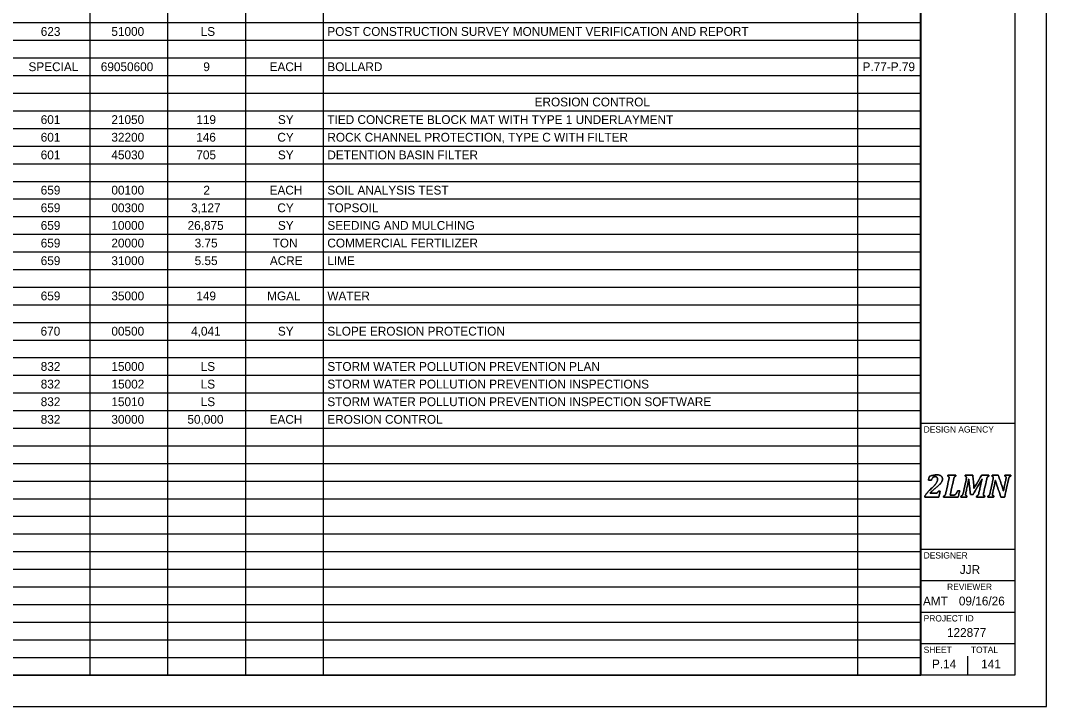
# Model space of a CAD drawing. Extents: x 0 to 34, y 0 to 22.
# Drawn here: x 17.71 to 34, y 0 to 10.89 of the extents above; entities that cross this region are included whole.
import ezdxf

# ---------------------------------------------------------------- set-up
doc = ezdxf.new("R2010")
doc.units = 0
for name, color, linetype in [('SH_Border', 7, 'Continuous'), ('SH_Cut_Line', 7, 'Continuous'), ('SH_Data', 7, 'Continuous'), ('SH_Text', 7, 'Continuous')]:
    doc.layers.add(name, color=color, linetype=linetype)

msp = doc.modelspace()

# ---------------------------------------------------------------- linework, layer by layer
at = {"layer": 'SH_Border'}
for p, q in [((32, 0.5), (32, 21.5)), ((32, 4.5), (33.5, 4.5)), ((32, 2.5), (33.5, 2.5)), ((32, 2), (33.5, 2)), ((32, 1.5), (33.5, 1.5)), ((32, 1), (33.5, 1))]:
    msp.add_line(p, q, dxfattribs=at)
msp.add_lwpolyline([(1.5, 21.5), (33.5, 21.5), (33.5, 0.5), (1.5, 0.5)], close=True, dxfattribs=at)
at = {"layer": 'SH_Cut_Line'}
msp.add_lwpolyline([(0, 0), (34, 0), (34, 22), (0, 22)], close=True, dxfattribs=at)
at = {"layer": 'SH_Data'}
for p, q in [((32.75, 3.5), (32.75, 3.5)), ((32.375, 0.675), (32.375, 0.675)), ((32.75, 0.5), (32.75, 0.8))]:
    msp.add_line(p, q, dxfattribs=at)
for points in [[(32.237, 3.388), (32.246, 3.388), (32.253, 3.389), (32.258, 3.39), (32.263, 3.392), (32.267, 3.394), (32.27, 3.397), (32.273, 3.401), (32.277, 3.408), (32.281, 3.417), (32.281, 3.417), (32.312, 3.417), (32.312, 3.417), (32.312, 3.417), (32.29, 3.326), (32.29, 3.326), (32.29, 3.326), (32.066, 3.326), (32.066, 3.326), (32.066, 3.326), (32.069, 3.343), (32.069, 3.343), (32.078, 3.358), (32.091, 3.375), (32.106, 3.394), (32.122, 3.412), (32.144, 3.435), (32.172, 3.462), (32.197, 3.486), (32.217, 3.506), (32.23, 3.521), (32.243, 3.537), (32.253, 3.551), (32.259, 3.566), (32.266, 3.58), (32.269, 3.595), (32.269, 3.61), (32.269, 3.622), (32.266, 3.632), (32.26, 3.64), (32.253, 3.647), (32.245, 3.65), (32.234, 3.65), (32.22, 3.65), (32.208, 3.646), (32.198, 3.636), (32.188, 3.627), (32.18, 3.613), (32.172, 3.593), (32.172, 3.593), (32.126, 3.593), (32.126, 3.593), (32.126, 3.593), (32.14, 3.654), (32.14, 3.654), (32.166, 3.663), (32.188, 3.669), (32.205, 3.673), (32.223, 3.676), (32.24, 3.678), (32.258, 3.678), (32.278, 3.678), (32.295, 3.675), (32.309, 3.669), (32.322, 3.664), (32.332, 3.656), (32.339, 3.646), (32.345, 3.637), (32.348, 3.626), (32.348, 3.613), (32.348, 3.602), (32.346, 3.591), (32.342, 3.581), (32.339, 3.571), (32.333, 3.56), (32.324, 3.549), (32.315, 3.539), (32.304, 3.526), (32.289, 3.513), (32.275, 3.499), (32.254, 3.482), (32.228, 3.46), (32.216, 3.45), (32.202, 3.438), (32.188, 3.425), (32.174, 3.412), (32.162, 3.4), (32.154, 3.391), (32.154, 3.391), (32.153, 3.388), (32.153, 3.388), (32.153, 3.388), (32.237, 3.388), (32.237, 3.388)], [(32.237, 3.388), (32.237, 3.388), (32.153, 3.388), (32.153, 3.388), (32.153, 3.388), (32.154, 3.391), (32.154, 3.391), (32.162, 3.4), (32.174, 3.412), (32.188, 3.425), (32.202, 3.438), (32.216, 3.45), (32.228, 3.46), (32.254, 3.482), (32.275, 3.499), (32.289, 3.513), (32.304, 3.526), (32.315, 3.539), (32.324, 3.549), (32.333, 3.56), (32.339, 3.571), (32.342, 3.581), (32.346, 3.591), (32.348, 3.602), (32.348, 3.613), (32.348, 3.626), (32.345, 3.637), (32.339, 3.646), (32.332, 3.656), (32.322, 3.664), (32.309, 3.669), (32.295, 3.675), (32.278, 3.678), (32.258, 3.678), (32.24, 3.678), (32.223, 3.676), (32.205, 3.673), (32.188, 3.669), (32.166, 3.663), (32.14, 3.654), (32.14, 3.654), (32.126, 3.593), (32.126, 3.593), (32.126, 3.593), (32.172, 3.593), (32.172, 3.593), (32.18, 3.613), (32.188, 3.627), (32.198, 3.636), (32.208, 3.646), (32.22, 3.65), (32.234, 3.65), (32.245, 3.65), (32.253, 3.647), (32.26, 3.64), (32.266, 3.632), (32.269, 3.622), (32.269, 3.61), (32.269, 3.595), (32.266, 3.58), (32.259, 3.566), (32.253, 3.551), (32.243, 3.537), (32.23, 3.521), (32.217, 3.506), (32.197, 3.486), (32.172, 3.462), (32.144, 3.435), (32.122, 3.412), (32.106, 3.394), (32.091, 3.375), (32.078, 3.358), (32.069, 3.343), (32.069, 3.343), (32.066, 3.326), (32.066, 3.326), (32.066, 3.326), (32.29, 3.326), (32.29, 3.326), (32.29, 3.326), (32.312, 3.417), (32.312, 3.417), (32.312, 3.417), (32.281, 3.417), (32.281, 3.417), (32.277, 3.408), (32.273, 3.401), (32.27, 3.397), (32.267, 3.394), (32.263, 3.392), (32.258, 3.39), (32.253, 3.389), (32.246, 3.388), (32.237, 3.388)], [(32.518, 3.356), (32.527, 3.356), (32.533, 3.357), (32.538, 3.358), (32.542, 3.36), (32.546, 3.362), (32.55, 3.365), (32.554, 3.368), (32.558, 3.372), (32.562, 3.377), (32.567, 3.382), (32.571, 3.388), (32.576, 3.397), (32.58, 3.405), (32.585, 3.415), (32.589, 3.427), (32.589, 3.427), (32.624, 3.427), (32.624, 3.427), (32.624, 3.427), (32.598, 3.326), (32.598, 3.326), (32.598, 3.326), (32.365, 3.326), (32.365, 3.326), (32.365, 3.326), (32.369, 3.343), (32.369, 3.343), (32.376, 3.345), (32.381, 3.348), (32.385, 3.351), (32.389, 3.355), (32.392, 3.36), (32.395, 3.366), (32.398, 3.373), (32.4, 3.382), (32.403, 3.395), (32.403, 3.395), (32.449, 3.605), (32.449, 3.605), (32.452, 3.615), (32.453, 3.625), (32.453, 3.635), (32.453, 3.642), (32.451, 3.647), (32.448, 3.651), (32.444, 3.654), (32.439, 3.656), (32.432, 3.657), (32.432, 3.657), (32.435, 3.674), (32.435, 3.674), (32.435, 3.674), (32.563, 3.674), (32.563, 3.674), (32.563, 3.674), (32.559, 3.657), (32.559, 3.657), (32.552, 3.655), (32.547, 3.652), (32.543, 3.649), (32.539, 3.645), (32.536, 3.64), (32.533, 3.634), (32.531, 3.627), (32.528, 3.618), (32.525, 3.605), (32.525, 3.605), (32.47, 3.356), (32.47, 3.356), (32.47, 3.356), (32.518, 3.356), (32.518, 3.356)], [(32.518, 3.356), (32.518, 3.356), (32.47, 3.356), (32.47, 3.356), (32.47, 3.356), (32.525, 3.605), (32.525, 3.605), (32.528, 3.618), (32.531, 3.627), (32.533, 3.634), (32.536, 3.64), (32.539, 3.645), (32.543, 3.649), (32.547, 3.652), (32.552, 3.655), (32.559, 3.657), (32.559, 3.657), (32.563, 3.674), (32.563, 3.674), (32.563, 3.674), (32.435, 3.674), (32.435, 3.674), (32.435, 3.674), (32.432, 3.657), (32.432, 3.657), (32.439, 3.656), (32.444, 3.654), (32.448, 3.651), (32.451, 3.647), (32.453, 3.642), (32.453, 3.635), (32.453, 3.625), (32.452, 3.615), (32.449, 3.605), (32.449, 3.605), (32.403, 3.395), (32.403, 3.395), (32.4, 3.382), (32.398, 3.373), (32.395, 3.366), (32.392, 3.36), (32.389, 3.355), (32.385, 3.351), (32.381, 3.348), (32.376, 3.345), (32.369, 3.343), (32.369, 3.343), (32.365, 3.326), (32.365, 3.326), (32.365, 3.326), (32.598, 3.326), (32.598, 3.326), (32.598, 3.326), (32.624, 3.427), (32.624, 3.427), (32.624, 3.427), (32.589, 3.427), (32.589, 3.427), (32.585, 3.415), (32.58, 3.405), (32.576, 3.397), (32.571, 3.388), (32.567, 3.382), (32.562, 3.377), (32.558, 3.372), (32.554, 3.368), (32.55, 3.365), (32.546, 3.362), (32.542, 3.36), (32.538, 3.358), (32.533, 3.357), (32.527, 3.356), (32.518, 3.356)], [(32.829, 3.674), (32.829, 3.674), (32.849, 3.461), (32.849, 3.461), (32.849, 3.461), (32.969, 3.674), (32.969, 3.674), (32.969, 3.674), (33.087, 3.674), (33.087, 3.674), (33.087, 3.674), (33.084, 3.657), (33.084, 3.657), (33.077, 3.655), (33.071, 3.652), (33.067, 3.649), (33.064, 3.645), (33.06, 3.64), (33.058, 3.634), (33.055, 3.627), (33.052, 3.618), (33.05, 3.605), (33.05, 3.605), (33.003, 3.395), (33.003, 3.395), (33.002, 3.39), (33.002, 3.387), (33.001, 3.384), (33.001, 3.382), (33.001, 3.379), (33, 3.376), (33, 3.373), (33, 3.369), (33, 3.365), (33, 3.358), (33.002, 3.353), (33.005, 3.349), (33.008, 3.346), (33.014, 3.344), (33.021, 3.343), (33.021, 3.343), (33.018, 3.326), (33.018, 3.326), (33.018, 3.326), (32.89, 3.326), (32.89, 3.326), (32.89, 3.326), (32.893, 3.343), (32.893, 3.343), (32.9, 3.345), (32.906, 3.348), (32.91, 3.351), (32.914, 3.355), (32.917, 3.36), (32.919, 3.366), (32.922, 3.373), (32.925, 3.382), (32.928, 3.395), (32.928, 3.395), (32.951, 3.502), (32.951, 3.502), (32.954, 3.513), (32.957, 3.529), (32.962, 3.548), (32.967, 3.568), (32.972, 3.588), (32.978, 3.609), (32.978, 3.609), (32.973, 3.609), (32.973, 3.609), (32.965, 3.594), (32.957, 3.579), (32.948, 3.563), (32.948, 3.563), (32.833, 3.364), (32.833, 3.364), (32.833, 3.364), (32.792, 3.364), (32.792, 3.364), (32.792, 3.364), (32.775, 3.518), (32.775, 3.518), (32.773, 3.537), (32.772, 3.554), (32.77, 3.569), (32.769, 3.583), (32.768, 3.597), (32.768, 3.611), (32.768, 3.611), (32.764, 3.611), (32.764, 3.611), (32.761, 3.596), (32.758, 3.578), (32.755, 3.558), (32.751, 3.538), (32.747, 3.521), (32.744, 3.507), (32.744, 3.507), (32.72, 3.395), (32.72, 3.395), (32.719, 3.39), (32.718, 3.387), (32.718, 3.384), (32.717, 3.382), (32.717, 3.379), (32.717, 3.376), (32.717, 3.373), (32.716, 3.369), (32.716, 3.365), (32.716, 3.358), (32.718, 3.353), (32.721, 3.349), (32.725, 3.346), (32.73, 3.344), (32.738, 3.343), (32.738, 3.343), (32.734, 3.326), (32.734, 3.326), (32.734, 3.326), (32.641, 3.326), (32.641, 3.326), (32.641, 3.326), (32.644, 3.343), (32.644, 3.343), (32.651, 3.345), (32.657, 3.348), (32.661, 3.351), (32.665, 3.355), (32.668, 3.36), (32.67, 3.366), (32.673, 3.373), (32.676, 3.382), (32.679, 3.395), (32.679, 3.395), (32.725, 3.605), (32.725, 3.605), (32.727, 3.615), (32.728, 3.625), (32.728, 3.635), (32.728, 3.642), (32.727, 3.647), (32.723, 3.651), (32.72, 3.654), (32.715, 3.656), (32.707, 3.657), (32.707, 3.657), (32.711, 3.674), (32.711, 3.674), (32.711, 3.674), (32.829, 3.674), (32.829, 3.674)], [(32.829, 3.674), (32.829, 3.674), (32.711, 3.674), (32.711, 3.674), (32.711, 3.674), (32.707, 3.657), (32.707, 3.657), (32.715, 3.656), (32.72, 3.654), (32.723, 3.651), (32.727, 3.647), (32.728, 3.642), (32.728, 3.635), (32.728, 3.625), (32.727, 3.615), (32.725, 3.605), (32.725, 3.605), (32.679, 3.395), (32.679, 3.395), (32.676, 3.382), (32.673, 3.373), (32.67, 3.366), (32.668, 3.36), (32.665, 3.355), (32.661, 3.351), (32.657, 3.348), (32.651, 3.345), (32.644, 3.343), (32.644, 3.343), (32.641, 3.326), (32.641, 3.326), (32.641, 3.326), (32.734, 3.326), (32.734, 3.326), (32.734, 3.326), (32.738, 3.343), (32.738, 3.343), (32.73, 3.344), (32.725, 3.346), (32.721, 3.349), (32.718, 3.353), (32.716, 3.358), (32.716, 3.365), (32.716, 3.369), (32.717, 3.373), (32.717, 3.376), (32.717, 3.379), (32.717, 3.382), (32.718, 3.384), (32.718, 3.387), (32.719, 3.39), (32.72, 3.395), (32.72, 3.395), (32.744, 3.507), (32.744, 3.507), (32.747, 3.521), (32.751, 3.538), (32.755, 3.558), (32.758, 3.578), (32.761, 3.596), (32.764, 3.611), (32.764, 3.611), (32.768, 3.611), (32.768, 3.611), (32.768, 3.597), (32.769, 3.583), (32.77, 3.569), (32.772, 3.554), (32.773, 3.537), (32.775, 3.518), (32.775, 3.518), (32.792, 3.364), (32.792, 3.364), (32.792, 3.364), (32.833, 3.364), (32.833, 3.364), (32.833, 3.364), (32.948, 3.563), (32.948, 3.563), (32.957, 3.579), (32.965, 3.594), (32.973, 3.609), (32.973, 3.609), (32.978, 3.609), (32.978, 3.609), (32.972, 3.588), (32.967, 3.568), (32.962, 3.548), (32.957, 3.529), (32.954, 3.513), (32.951, 3.502), (32.951, 3.502), (32.928, 3.395), (32.928, 3.395), (32.925, 3.382), (32.922, 3.373), (32.919, 3.366), (32.917, 3.36), (32.914, 3.355), (32.91, 3.351), (32.906, 3.348), (32.9, 3.345), (32.893, 3.343), (32.893, 3.343), (32.89, 3.326), (32.89, 3.326), (32.89, 3.326), (33.018, 3.326), (33.018, 3.326), (33.018, 3.326), (33.021, 3.343), (33.021, 3.343), (33.014, 3.344), (33.008, 3.346), (33.005, 3.349), (33.002, 3.353), (33, 3.358), (33, 3.365), (33, 3.369), (33, 3.373), (33, 3.376), (33.001, 3.379), (33.001, 3.382), (33.001, 3.384), (33.002, 3.387), (33.002, 3.39), (33.003, 3.395), (33.003, 3.395), (33.05, 3.605), (33.05, 3.605), (33.052, 3.618), (33.055, 3.627), (33.058, 3.634), (33.06, 3.64), (33.064, 3.645), (33.067, 3.649), (33.071, 3.652), (33.077, 3.655), (33.084, 3.657), (33.084, 3.657), (33.087, 3.674), (33.087, 3.674), (33.087, 3.674), (32.969, 3.674), (32.969, 3.674), (32.969, 3.674), (32.849, 3.461), (32.849, 3.461), (32.849, 3.461), (32.829, 3.674), (32.829, 3.674)], [(33.137, 3.674), (33.137, 3.674), (33.234, 3.674), (33.234, 3.674), (33.234, 3.674), (33.283, 3.53), (33.283, 3.53), (33.296, 3.49), (33.307, 3.456), (33.315, 3.426), (33.315, 3.426), (33.318, 3.426), (33.318, 3.426), (33.323, 3.455), (33.329, 3.488), (33.337, 3.523), (33.337, 3.523), (33.355, 3.605), (33.355, 3.605), (33.357, 3.615), (33.358, 3.625), (33.358, 3.635), (33.358, 3.642), (33.357, 3.647), (33.353, 3.651), (33.35, 3.654), (33.345, 3.656), (33.337, 3.657), (33.337, 3.657), (33.341, 3.674), (33.341, 3.674), (33.341, 3.674), (33.434, 3.674), (33.434, 3.674), (33.434, 3.674), (33.431, 3.657), (33.431, 3.657), (33.424, 3.655), (33.418, 3.652), (33.414, 3.649), (33.41, 3.645), (33.407, 3.64), (33.405, 3.634), (33.402, 3.627), (33.399, 3.618), (33.396, 3.605), (33.396, 3.605), (33.335, 3.326), (33.335, 3.326), (33.335, 3.326), (33.277, 3.326), (33.277, 3.326), (33.277, 3.326), (33.216, 3.504), (33.216, 3.504), (33.211, 3.518), (33.207, 3.531), (33.204, 3.543), (33.2, 3.556), (33.195, 3.571), (33.19, 3.59), (33.19, 3.59), (33.186, 3.59), (33.186, 3.59), (33.185, 3.579), (33.182, 3.563), (33.179, 3.543), (33.175, 3.523), (33.17, 3.501), (33.165, 3.478), (33.165, 3.478), (33.147, 3.395), (33.147, 3.395), (33.146, 3.39), (33.145, 3.387), (33.145, 3.384), (33.144, 3.382), (33.144, 3.379), (33.144, 3.376), (33.143, 3.373), (33.143, 3.369), (33.143, 3.365), (33.143, 3.358), (33.145, 3.353), (33.148, 3.349), (33.152, 3.346), (33.157, 3.344), (33.164, 3.343), (33.164, 3.343), (33.161, 3.326), (33.161, 3.326), (33.161, 3.326), (33.067, 3.326), (33.067, 3.326), (33.067, 3.326), (33.071, 3.343), (33.071, 3.343), (33.078, 3.345), (33.083, 3.348), (33.087, 3.351), (33.091, 3.355), (33.094, 3.36), (33.097, 3.366), (33.1, 3.373), (33.102, 3.382), (33.105, 3.395), (33.105, 3.395), (33.151, 3.605), (33.151, 3.605), (33.154, 3.615), (33.155, 3.625), (33.155, 3.635), (33.155, 3.642), (33.153, 3.647), (33.15, 3.651), (33.146, 3.654), (33.141, 3.656), (33.134, 3.657), (33.134, 3.657), (33.137, 3.674), (33.137, 3.674)], [(33.137, 3.674), (33.137, 3.674), (33.134, 3.657), (33.134, 3.657), (33.141, 3.656), (33.146, 3.654), (33.15, 3.651), (33.153, 3.647), (33.155, 3.642), (33.155, 3.635), (33.155, 3.625), (33.154, 3.615), (33.151, 3.605), (33.151, 3.605), (33.105, 3.395), (33.105, 3.395), (33.102, 3.382), (33.1, 3.373), (33.097, 3.366), (33.094, 3.36), (33.091, 3.355), (33.087, 3.351), (33.083, 3.348), (33.078, 3.345), (33.071, 3.343), (33.071, 3.343), (33.067, 3.326), (33.067, 3.326), (33.067, 3.326), (33.161, 3.326), (33.161, 3.326), (33.161, 3.326), (33.164, 3.343), (33.164, 3.343), (33.157, 3.344), (33.152, 3.346), (33.148, 3.349), (33.145, 3.353), (33.143, 3.358), (33.143, 3.365), (33.143, 3.369), (33.143, 3.373), (33.144, 3.376), (33.144, 3.379), (33.144, 3.382), (33.145, 3.384), (33.145, 3.387), (33.146, 3.39), (33.147, 3.395), (33.147, 3.395), (33.165, 3.478), (33.165, 3.478), (33.17, 3.501), (33.175, 3.523), (33.179, 3.543), (33.182, 3.563), (33.185, 3.579), (33.186, 3.59), (33.186, 3.59), (33.19, 3.59), (33.19, 3.59), (33.195, 3.571), (33.2, 3.556), (33.204, 3.543), (33.207, 3.531), (33.211, 3.518), (33.216, 3.504), (33.216, 3.504), (33.277, 3.326), (33.277, 3.326), (33.277, 3.326), (33.335, 3.326), (33.335, 3.326), (33.335, 3.326), (33.396, 3.605), (33.396, 3.605), (33.399, 3.618), (33.402, 3.627), (33.405, 3.634), (33.407, 3.64), (33.41, 3.645), (33.414, 3.649), (33.418, 3.652), (33.424, 3.655), (33.431, 3.657), (33.431, 3.657), (33.434, 3.674), (33.434, 3.674), (33.434, 3.674), (33.341, 3.674), (33.341, 3.674), (33.341, 3.674), (33.337, 3.657), (33.337, 3.657), (33.345, 3.656), (33.35, 3.654), (33.353, 3.651), (33.357, 3.647), (33.358, 3.642), (33.358, 3.635), (33.358, 3.625), (33.357, 3.615), (33.355, 3.605), (33.355, 3.605), (33.337, 3.523), (33.337, 3.523), (33.329, 3.488), (33.323, 3.455), (33.318, 3.426), (33.318, 3.426), (33.315, 3.426), (33.315, 3.426), (33.307, 3.456), (33.296, 3.49), (33.283, 3.53), (33.283, 3.53), (33.234, 3.674), (33.234, 3.674), (33.234, 3.674), (33.137, 3.674), (33.137, 3.674)]]:
    msp.add_open_spline(points, degree=3, dxfattribs=at)
at = {"layer": 'SH_Text'}
for p, q in [((18.811, 21.5), (18.811, 0.5)), ((20.046, 21.5), (20.046, 0.5)), ((21.281, 21.5), (21.281, 0.5)), ((22.516, 21.5), (22.516, 0.5)), ((30.999, 21.5), (30.999, 0.5)), ((32.004, 21.5), (32.004, 0.5)), ((1.5, 10.86), (32.004, 10.86)), ((1.5, 10.58), (32.004, 10.58)), ((1.5, 10.3), (32.004, 10.3)), ((1.5, 10.02), (32.004, 10.02)), ((1.5, 9.74), (32.004, 9.74)), ((1.5, 9.46), (32.004, 9.46)), ((1.5, 9.18), (32.004, 9.18)), ((1.5, 8.9), (32.004, 8.9)), ((1.5, 8.62), (32.004, 8.62)), ((1.5, 8.34), (32.004, 8.34)), ((1.5, 8.06), (32.004, 8.06)), ((1.5, 7.78), (32.004, 7.78)), ((1.5, 7.5), (32.004, 7.5)), ((1.5, 7.22), (32.004, 7.22)), ((1.5, 6.94), (32.004, 6.94)), ((1.5, 6.66), (32.004, 6.66)), ((1.5, 6.38), (32.004, 6.38)), ((1.5, 6.1), (32.004, 6.1)), ((1.5, 5.82), (32.004, 5.82)), ((1.5, 5.54), (32.004, 5.54)), ((1.5, 5.26), (32.004, 5.26)), ((1.5, 4.98), (32.004, 4.98)), ((1.5, 4.7), (32.004, 4.7)), ((1.5, 4.42), (32.004, 4.42)), ((1.5, 4.14), (32.004, 4.14)), ((1.5, 3.86), (32.004, 3.86)), ((1.5, 3.58), (32.004, 3.58)), ((1.5, 3.3), (32.004, 3.3)), ((1.5, 3.02), (32.004, 3.02)), ((1.5, 2.74), (32.004, 2.74)), ((1.5, 2.46), (32.004, 2.46)), ((1.5, 2.18), (32.004, 2.18)), ((1.5, 1.9), (32.004, 1.9)), ((1.5, 1.62), (32.004, 1.62)), ((1.5, 1.34), (32.004, 1.34)), ((1.5, 1.06), (32.004, 1.06)), ((1.5, 0.78), (32.004, 0.78)), ((1.5, 0.5), (32.004, 0.5))]:
    msp.add_line(p, q, dxfattribs=at)

# ---------------------------------------------------------------- texts
at = {"layer": 'SH_Data'}
for s, height, p in [('DESIGN AGENCY', 0.1, (32.05, 4.35)), ('DESIGNER', 0.1, (32.05, 2.35)), ('JJR', 0.14, (32.624, 2.105)), ('REVIEWER', 0.1, (32.422, 1.85)), ('AMT', 0.14, (32.039, 1.605)), ('09/16/26', 0.14, (32.609, 1.605)), ('PROJECT ID', 0.1, (32.05, 1.35)), ('122877', 0.14, (32.42, 1.105)), ('SHEET', 0.1, (32.05, 0.85)), ('TOTAL', 0.1, (32.8, 0.85)), ('P.14', 0.14, (32.182, 0.605)), ('141', 0.14, (32.963, 0.605))]:
    msp.add_text(s, height=height, dxfattribs=at).set_placement(p)
at = {"layer": 'SH_Text'}
for s, p in [('623', (18.032, 10.65)), ('51000', (19.153, 10.65)), ('LS', (20.571, 10.65)), ('POST CONSTRUCTION SURVEY MONUMENT VERIFICATION AND REPORT', (22.582, 10.65)), ('SPECIAL', (17.837, 10.09)), ('69050600', (18.985, 10.09)), ('9', (20.613, 10.09)), ('EACH', (21.665, 10.09)), ('BOLLARD', (22.582, 10.09)), ('P.77-P.79', (31.08, 10.09)), ('EROSION CONTROL', (25.873, 9.53)), ('601', (18.031, 9.25)), ('21050', (19.153, 9.25)), ('119', (20.502, 9.25)), ('SY', (21.797, 9.25)), ('TIED CONCRETE BLOCK MAT WITH TYPE 1 UNDERLAYMENT', (22.582, 9.25)), ('601', (18.031, 8.97)), ('32200', (19.153, 8.97)), ('146', (20.5, 8.97)), ('CY', (21.788, 8.97)), ('ROCK CHANNEL PROTECTION, TYPE C WITH FILTER', (22.582, 8.97)), ('601', (18.031, 8.69)), ('45030', (19.153, 8.69)), ('705', (20.502, 8.69)), ('SY', (21.797, 8.69)), ('DETENTION BASIN FILTER', (22.582, 8.69)), ('659', (18.031, 8.13)), ('00100', (19.153, 8.13)), ('2', (20.614, 8.13)), ('EACH', (21.665, 8.13)), ('SOIL ANALYSIS TEST', (22.582, 8.13)), ('659', (18.031, 7.85)), ('00300', (19.153, 7.85)), ('3,127', (20.418, 7.85)), ('CY', (21.788, 7.85)), ('TOPSOIL', (22.582, 7.85)), ('659', (18.031, 7.57)), ('10000', (19.153, 7.57)), ('26,875', (20.363, 7.57)), ('SY', (21.797, 7.57)), ('SEEDING AND MULCHING', (22.582, 7.57)), ('659', (18.031, 7.29)), ('20000', (19.153, 7.29)), ('3.75', (20.475, 7.29)), ('TON', (21.713, 7.29)), ('COMMERCIAL FERTILIZER', (22.582, 7.29)), ('659', (18.031, 7.01)), ('31000', (19.153, 7.01)), ('5.55', (20.475, 7.01)), ('ACRE', (21.669, 7.01)), ('LIME', (22.582, 7.01)), ('659', (18.031, 6.45)), ('35000', (19.153, 6.45)), ('149', (20.502, 6.45)), ('MGAL', (21.626, 6.45)), ('WATER', (22.582, 6.45)), ('670', (18.029, 5.89)), ('00500', (19.153, 5.89)), ('4,041', (20.419, 5.89)), ('SY', (21.797, 5.89)), ('SLOPE EROSION PROTECTION', (22.582, 5.89)), ('832', (18.031, 5.33)), ('15000', (19.153, 5.33)), ('LS', (20.571, 5.33)), ('STORM WATER POLLUTION PREVENTION PLAN', (22.582, 5.33)), ('832', (18.031, 5.05)), ('15002', (19.155, 5.05)), ('LS', (20.571, 5.05)), ('STORM WATER POLLUTION PREVENTION INSPECTIONS', (22.582, 5.05)), ('832', (18.031, 4.77)), ('15010', (19.153, 4.77)), ('LS', (20.571, 4.77)), ('STORM WATER POLLUTION PREVENTION INSPECTION SOFTWARE', (22.582, 4.77)), ('832', (18.031, 4.49)), ('30000', (19.153, 4.49)), ('50,000', (20.36, 4.49)), ('EACH', (21.665, 4.49)), ('EROSION CONTROL', (22.582, 4.49))]:
    msp.add_text(s, height=0.14, dxfattribs=at).set_placement(p)

doc.saveas('drawing.dxf')
